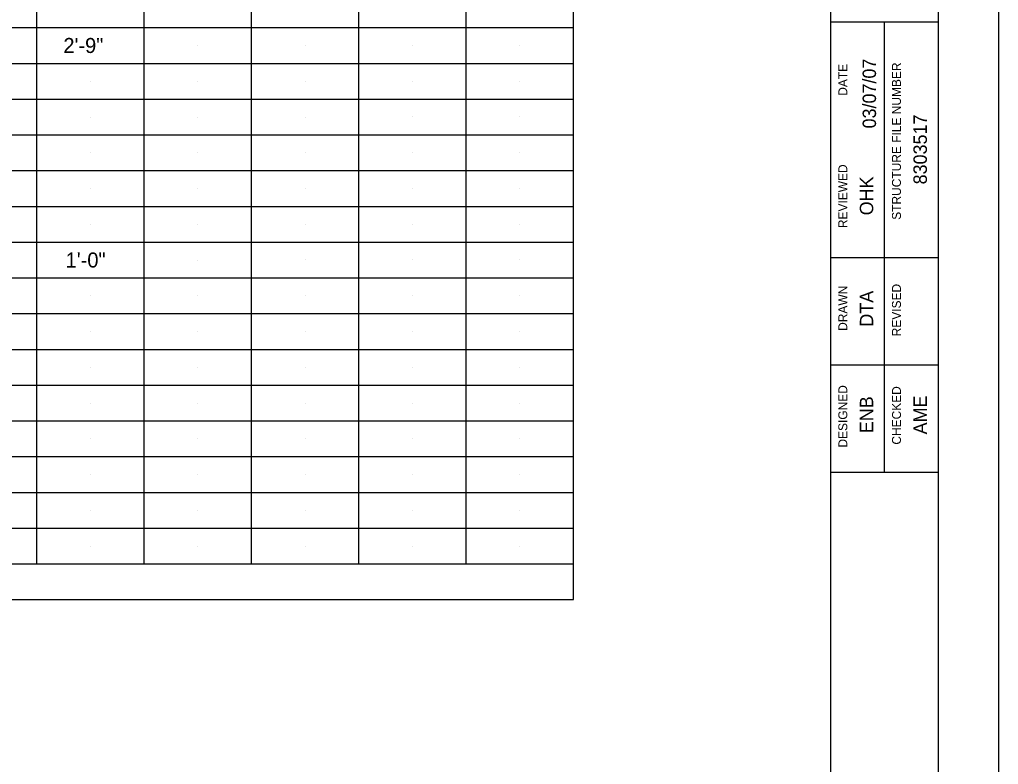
# Model space of a CAD drawing. Extents: x -9.2 to 26.7, y -0.9 to 21.1.
# Drawn here: x 16.98 to 26.1, y 10.19 to 17.13 of the extents above; entities that cross this region are included whole.
import ezdxf

# ---------------------------------------------------------------- set-up
doc = ezdxf.new("R2010")
doc.units = 0
for name, color, linetype in [('BR_P_Gen_Text', 7, 'Continuous'), ('SC_Scratch1', 7, 'Continuous'), ('SH_Border', 7, 'Continuous'), ('SH_Cut_Line', 7, 'Continuous'), ('SH_Data', 7, 'Continuous')]:
    doc.layers.add(name, color=color, linetype=linetype)

msp = doc.modelspace()

# ---------------------------------------------------------------- linework, layer by layer
at = {"layer": 'BR_P_Gen_Text'}
for p, q in [((22.1368, 11.7231), (22.1367, 20.2066)), ((17.1372, 12.0564), (17.1372, 18.3896)), ((18.1372, 12.0564), (18.1371, 18.3896)), ((19.1371, 12.0564), (19.137, 18.3897)), ((20.137, 12.0564), (20.1369, 18.3898)), ((21.1369, 12.0564), (21.1368, 18.3898)), ((7.6374, 17.0565), (22.1368, 17.0565)), ((7.6374, 16.7232), (22.1368, 16.7232)), ((7.6374, 16.3898), (22.1368, 16.3899)), ((7.6375, 16.0565), (22.1368, 16.0566)), ((7.6375, 15.7232), (22.1368, 15.7233)), ((7.6374, 15.3898), (22.1368, 15.3899)), ((7.6374, 15.0565), (22.1368, 15.0565)), ((7.6374, 14.7232), (22.1368, 14.7232)), ((7.6374, 14.3899), (22.1368, 14.3899)), ((7.6374, 14.0565), (22.1368, 14.0565)), ((7.6374, 13.7232), (22.1368, 13.7232)), ((7.6375, 13.3898), (22.1368, 13.3898)), ((7.6374, 13.0565), (22.1368, 13.0565)), ((7.6374, 12.7231), (22.1368, 12.7232)), ((7.6374, 12.3898), (22.1368, 12.3899)), ((7.6374, 12.0565), (22.1368, 12.0565)), ((7.6375, 11.7231), (22.1368, 11.7232))]:
    msp.add_line(p, q, dxfattribs=at)
at = {"layer": 'SC_Scratch1'}
for p, q in [((17.6371, 16.8897), (17.6371, 16.8897)), ((18.6371, 16.8897), (18.6371, 16.8897)), ((19.637, 16.8897), (19.637, 16.8897)), ((20.6368, 16.8897), (20.6368, 16.8897)), ((21.6368, 16.8897), (21.6368, 16.8897)), ((21.6368, 16.8897), (21.6368, 16.8897)), ((17.6371, 16.5563), (17.6371, 16.5563)), ((18.637, 16.5563), (18.637, 16.5563)), ((19.6369, 16.5564), (19.6369, 16.5564)), ((20.6368, 16.5564), (20.6368, 16.5564)), ((21.6369, 16.5564), (21.6369, 16.5564)), ((21.6369, 16.5564), (21.6369, 16.5564)), ((17.6372, 16.223), (17.6372, 16.223)), ((18.637, 16.223), (18.637, 16.223)), ((19.6369, 16.223), (19.6369, 16.223)), ((20.6368, 16.2231), (20.6368, 16.2231)), ((21.6369, 16.2231), (21.6369, 16.2231)), ((21.6369, 16.2231), (21.6369, 16.2231)), ((17.6371, 15.8896), (17.6371, 15.8896)), ((18.637, 15.8896), (18.637, 15.8896)), ((19.6369, 15.8897), (19.6369, 15.8897)), ((20.6368, 15.8898), (20.6368, 15.8898)), ((21.6369, 15.8897), (21.6369, 15.8897)), ((21.6369, 15.8897), (21.6369, 15.8897)), ((17.6371, 15.5563), (17.6371, 15.5563)), ((18.637, 15.5564), (18.637, 15.5564)), ((19.6369, 15.5564), (19.6369, 15.5564)), ((20.6368, 15.5564), (20.6368, 15.5564)), ((21.6369, 15.5564), (21.6369, 15.5564)), ((21.6369, 15.5564), (21.6369, 15.5564)), ((17.6371, 15.223), (17.6371, 15.223)), ((18.637, 15.223), (18.637, 15.223)), ((19.6369, 15.2231), (19.6369, 15.2231)), ((20.6369, 15.2231), (20.6369, 15.2231)), ((21.6369, 15.2231), (21.6369, 15.2231)), ((21.6369, 15.2231), (21.6369, 15.2231)), ((17.6371, 14.8897), (17.6371, 14.8897)), ((18.637, 14.8897), (18.637, 14.8897)), ((19.6369, 14.8898), (19.6369, 14.8898)), ((20.6369, 14.8898), (20.6369, 14.8898)), ((21.6368, 14.8898), (21.6368, 14.8898)), ((21.6368, 14.8898), (21.6368, 14.8898)), ((17.6372, 14.5563), (17.6372, 14.5563)), ((18.6371, 14.5563), (18.6371, 14.5563)), ((19.637, 14.5564), (19.637, 14.5564)), ((20.6368, 14.5564), (20.6368, 14.5564)), ((21.6368, 14.5564), (21.6368, 14.5564)), ((21.6368, 14.5564), (21.6368, 14.5564)), ((17.6371, 14.223), (17.6371, 14.223)), ((18.637, 14.223), (18.637, 14.223)), ((19.6369, 14.223), (19.6369, 14.223)), ((20.6368, 14.223), (20.6368, 14.223)), ((21.6368, 14.2231), (21.6368, 14.2231)), ((21.6368, 14.2231), (21.6368, 14.2231)), ((17.6371, 13.8897), (17.6371, 13.8897)), ((18.637, 13.8896), (18.637, 13.8896)), ((19.6369, 13.8897), (19.6369, 13.8897)), ((20.6368, 13.8897), (20.6368, 13.8897)), ((21.6369, 13.8897), (21.6369, 13.8897)), ((21.6369, 13.8897), (21.6369, 13.8897)), ((17.6371, 13.5563), (17.6371, 13.5563)), ((18.637, 13.5563), (18.637, 13.5563)), ((19.6369, 13.5564), (19.6369, 13.5564)), ((20.6369, 13.5564), (20.6369, 13.5564)), ((21.6369, 13.5564), (21.6369, 13.5564)), ((21.6369, 13.5564), (21.6369, 13.5564)), ((17.6371, 13.223), (17.6371, 13.223)), ((18.637, 13.223), (18.637, 13.223)), ((19.6369, 13.223), (19.6369, 13.223)), ((20.6369, 13.223), (20.6369, 13.223)), ((21.6369, 13.2231), (21.6369, 13.2231)), ((21.6369, 13.2231), (21.6369, 13.2231)), ((17.6371, 12.8896), (17.6371, 12.8896)), ((18.6371, 12.8896), (18.6371, 12.8896)), ((19.637, 12.8897), (19.637, 12.8897)), ((20.6369, 12.8897), (20.6369, 12.8897)), ((21.6369, 12.8897), (21.6369, 12.8897)), ((21.6369, 12.8897), (21.6369, 12.8897)), ((17.6371, 12.5563), (17.6371, 12.5563)), ((17.6371, 12.5563), (17.6371, 12.5563)), ((18.6371, 12.5563), (18.6371, 12.5563)), ((19.637, 12.5564), (19.637, 12.5564)), ((20.6369, 12.5564), (20.6369, 12.5564)), ((21.6368, 12.5563), (21.6368, 12.5563)), ((21.6368, 12.5563), (21.6368, 12.5563)), ((17.6371, 12.223), (17.6371, 12.223)), ((18.6371, 12.2229), (18.6371, 12.2229)), ((19.637, 12.223), (19.637, 12.223)), ((20.6369, 12.2231), (20.6369, 12.2231)), ((21.6369, 12.223), (21.6369, 12.223)), ((21.6369, 12.223), (21.6369, 12.223))]:
    msp.add_line(p, q, dxfattribs=at)
at = {"layer": 'SH_Border'}
for p, q in [((24.5337, -0.3882), (24.5337, 20.6118)), ((24.5337, 17.1118), (25.5337, 17.1118)), ((25.0337, 12.9118), (25.0337, 17.1118)), ((24.5337, 14.9118), (25.5337, 14.9118)), ((24.5337, 13.9118), (25.5337, 13.9118)), ((24.5337, 12.9118), (25.5337, 12.9118))]:
    msp.add_line(p, q, dxfattribs=at)
msp.add_lwpolyline([(-5.9663, 20.6118), (25.5337, 20.6118), (25.5337, -0.3882), (-5.9663, -0.3882)], close=True, dxfattribs=at)
at = {"layer": 'SH_Cut_Line'}
msp.add_lwpolyline([(26.0962, -0.7382), (-7.9038, -0.7382), (-7.9038, 20.9118), (26.0962, 20.9118)], close=True, dxfattribs=at)

# ---------------------------------------------------------------- texts
at = {"layer": 'BR_P_Gen_Text'}
for s, p in [('2\'-9"', (17.3835, 16.8199)), ('1\'-0"', (17.4045, 14.8198))]:
    msp.add_text(s, height=0.14, dxfattribs=at).set_placement(p)
at = {"layer": 'SH_Data'}
for s, height, p in [('DATE', 0.0833, (24.6879, 16.4211)), ('03/07/07', 0.125, (24.9558, 16.1164)), ('STRUCTURE FILE NUMBER', 0.0833, (25.1879, 15.2648)), ('8303517', 0.125, (25.4296, 15.5949)), ('REVIEWED', 0.0833, (24.6879, 15.187)), ('OHK', 0.125, (24.9296, 15.3063)), ('DRAWN', 0.0833, (24.6879, 14.2294)), ('DTA', 0.125, (24.9296, 14.2684)), ('REVISED', 0.0833, (25.1879, 14.1783)), ('DESIGNED', 0.0833, (24.6879, 13.1409)), ('CHECKED', 0.0833, (25.1879, 13.1684)), ('ENB', 0.125, (24.9296, 13.2753)), ('AME', 0.125, (25.4296, 13.264))]:
    msp.add_text(s, height=height, rotation=90, dxfattribs=at).set_placement(p)

doc.saveas('drawing.dxf')
